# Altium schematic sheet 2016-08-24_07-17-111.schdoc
size 331 x 152 mm; SheetNumber: 1; SheetTotal: 1
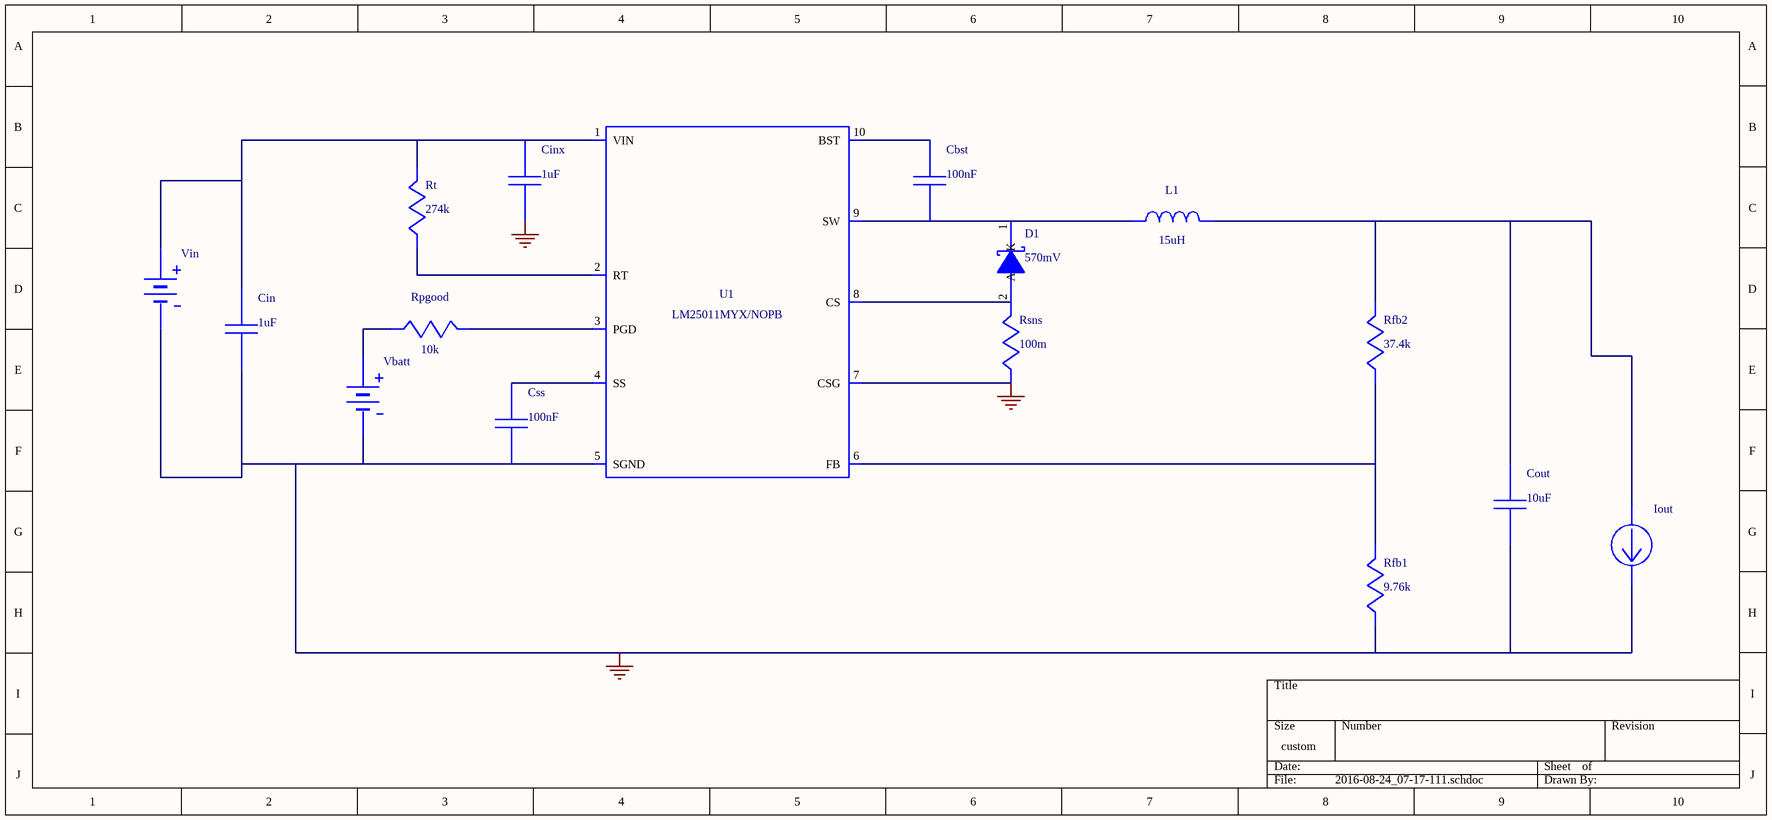
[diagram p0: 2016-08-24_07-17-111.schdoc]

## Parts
Cbst  value 100nF  (hidden comment: GRM21BR71E104KA01L)
Cin  value 1uF  (hidden comment: GRM31MR71H105KA88L)
Cinx  value 1uF  (hidden comment: GMK212B7105KG-T)
Cout  value 10uF  (hidden comment: GRM21BR61C106KE15L)
Css  value 100nF  (hidden comment: GRM21BR71E104KA01L)
D1  value 570mV  (hidden comment: PMEG6010CEH,115)
Iout  WB_CURRENT_LOAD  (value not drawn)
L1  value 15uH  (hidden comment: SRN6045-150M)
Rfb1  value 9.76k  (hidden comment: CRCW04029K76FKED)
Rfb2  value 37.4k  (hidden comment: CRCW040237K4FKED)
Rpgood  value 10k  (hidden comment: CRCW040210K0FKED)
Rsns  value 100m  (hidden comment: ERJ-3RSFR10V)
Rt  value 274k  (hidden comment: CRCW0402274KFKED)
U1  LM25011MYX/NOPB
Vbatt  WB_PRIMITIVE_BATTERY  (value not drawn)
Vin  WB_BATTERY  (value not drawn)

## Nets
0: Cin.2 Cinx.2 Cout.2 Css.2 Iout.2(-) Rfb1.2 Rsns.2 U1.5(SGND) U1.7(CSG) U1.11(DAP) Vbatt.2(-) Vin.2(-)
NetCbst_1: Cbst.1 U1.10(BST)
NetCbst_2: Cbst.2 D1.1(K) L1.1 U1.9(SW)
NetCin_1: Cin.1 Cinx.1 Rt.1 U1.1(VIN) Vin.1(+)
NetCout_1: Cout.1 Iout.1(+) L1.2 Rfb2.1
NetCss_1: Css.1 U1.4(SS)
NetD1_2: D1.2(A) Rsns.1 U1.8(CS)
NetRfb1_1: Rfb1.1 Rfb2.2 U1.6(FB)
NetRpgood_1: Rpgood.1 U1.3(PGD)
NetRpgood_2: Rpgood.2 Vbatt.1(+)
NetRt_2: Rt.2 U1.2(RT)

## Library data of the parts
Cbst Css = GRM21BR71E104KA01L: GRM21BR71E104KA0; Manufacturer Name: MuRata
Cin = GRM31MR71H105KA88L: GRM31MR71H105KA8; Manufacturer Name: MuRata
Cinx = GMK212B7105KG-T: Manufacturer Name: Taiyo Yuden
Cout = GRM21BR61C106KE15L: GRM21BR61C106KE1; Manufacturer Name: MuRata
D1 = PMEG6010CEH,115: Manufacturer Name: NXP Semiconductor
L1 = SRN6045-150M: Manufacturer Name: Bourns
Rfb1 = CRCW04029K76FKED: Manufacturer Name: Vishay-Dale
Rfb2 = CRCW040237K4FKED: Manufacturer Name: Vishay-Dale
Rpgood = CRCW040210K0FKED: Manufacturer Name: Vishay-Dale
Rsns = ERJ-3RSFR10V: Manufacturer Name: Panasonic
Rt = CRCW0402274KFKED: Manufacturer Name: Vishay-Dale
U1 = LM25011MYX/NOPB: Manufacturer Name: Texas Instruments
Vbatt = WB_PRIMITIVE_BATTERY: WB_PRIMITIVE_BAT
